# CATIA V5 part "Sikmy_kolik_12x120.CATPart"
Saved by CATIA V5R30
Part number: Sikmy_kolik_12x120
Definition: E 1032_12x120_1
Nomenclature: E 1032_12x120_1
Source: Unknown
Description: PART-E 1032_12x120_1-DESC
Bounding box of the stored display mesh (mm): x -7.5 to 7.5, y -7.49 to 7.49, z 0 to 120
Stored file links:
  E:\Bakalarka\Model\Forma_v7\Sikmy_kolik_12x120.CATPart
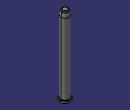
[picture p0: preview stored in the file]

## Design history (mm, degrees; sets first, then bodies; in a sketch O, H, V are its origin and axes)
Body1 "E 1032_12x120" (main body)
  Solid1: solid without history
